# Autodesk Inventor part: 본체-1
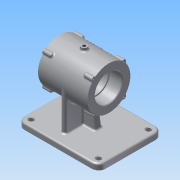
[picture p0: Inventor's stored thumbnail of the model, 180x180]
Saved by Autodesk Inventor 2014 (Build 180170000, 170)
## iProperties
Created: 2016-01
Part Number: 본체-1
Material: 알루미늄 6061
Document SubType Name: Modeling
Designer: Administrator
Density: 2.71 g/cm^3
Appearance: 알루미늄 - 평지
Mass: 1037.38 g
Surface Area: 821.121 cm^2
Volume: 382.798 cm^3
Author: Administrator
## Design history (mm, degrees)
sketch "스케치1"
  geometry: C1 r 37 at (0, 0); 1 further point
  constraints: 1 centre point, 1 coincident
  dimensions: "d0" = 74 diameter of C1
extrude "돌출1" new body sketch "스케치1" stored distance "d1" = 85; taper "d2" = 0 deg
sketch "스케치2"
  geometry: L1 (0, 0)-(26.163, 26.163); L2 (0, 0)-(37, 0); C1 r 3.5 at (26.163, 26.163)
  constraints: 4 end point, 1 centre point, 1 coincident, 1 equal length, 1 horizontal, 2 other
  dimensions: "d3" = 45 deg angle of L2 L1; "d4" = 7 diameter of C1
extrude "돌출2" join sketch "스케치2" distance "d5" = 15; taper "d6" = 0 deg
node "작업 평면1"
sketch "스케치3"
  geometry: L1 (55, 80)-(-55, 80); L2 (-55, 80)-(-55, -60); L3 (-55, -60)-(55, -60); L4 (55, -60)-(55, 80); L5 (23.574, 42.5)-(-23.574, 42.5) reference; 1 further point
  constraints: 8 end point, 2 parallel, 1 horizontal, 1 perpendicular
  dimensions: "d11" = 37.5 distance between parallel lines of L1 L5; "d12" = 140 distance between parallel lines of L3 L1; "d13" = 55 distance from line of point (0, 0) L4; "d14" = 110 distance between parallel lines of L2 L4
extrude "돌출3" join sketch "스케치3" distance "d15" = 10; taper "d16" = 0 deg
sketch "스케치4"
  geometry: L1 (37, 42.5)-(37, -42.5) reference; L2 (37, -42.5)-(-37, -42.5) reference; L3 (-37, -42.5)-(-37, 42.5) reference; L4 (-37, 42.5)-(37, 42.5) reference; L5 (-80, 80)-(-70, 80) reference; L6 (-70, 80)-(-70, -60) reference; L7 (-70, -60)-(-80, -60) reference; L8 (-80, -60)-(-80, 80) reference; L9 (-70, 25)-(-19.194, 16.953); L10 (-70, 0)-(0, 0); L11 (-70, -25)-(-19.194, -16.953); L12 (-19.194, 16.953)-(-19.194, -16.953); L13 (-70, -25)-(-70, 25)
  constraints: 10 end point, 2 perpendicular, 2 point on line, 2 symmetric about line, 1 collinear
  dimensions: "d17" = 25 distance of L9.start L10.start; "d18" = 99 deg angle of L6 L9; "d19" = 56.19381 distance between parallel lines of L1 L12
extrude "돌출4" join sketch "스케치4" stored distance "d20" = 12; taper "d21" = 0 deg
sketch "스케치5"
  geometry: L1 (55, -70)-(55, -80) reference; L2 (55, -80)-(-55, -80) reference; L3 (-55, -80)-(-55, -70) reference; L4 (-55, -70)-(-6, -70) reference; L5 (-6, -70)-(-6, -36.51) reference; L6 (6, -36.51)-(6, -70) reference; L7 (6, -70)-(55, -70) reference; L8 (-37, 0)-(37, 0); L9 (37, 0)-(37, -70); L10 (37, -70)-(-37, -70); L11 (-37, -70)-(-37, 0); A1 r 37 centre (0, 0) between (6, -36.51) and (-6, -36.51) reference; 2 further points
  constraints: 8 end point, 2 parallel, 2 tangent, 1 coincident, 1 horizontal, 1 midpoint, 1 perpendicular, 1 point on line
extrude "돌출5" join sketch "스케치5" stored distance "d22" = 8; taper "d23" = 0 deg
fillet "모깎기1" dims "d24" = 12
sketch "스케치7"
  geometry: C1 r 4 at (-43, 48); C2 r 4 at (43, 48); C3 r 4 at (43, -68); C4 r 4 at (-43, -68); A1 r 12 centre (-43, -68) between (-55, -68) and (-43, -80) reference; A2 r 12 centre (43, -68) between (43, -80) and (55, -68) reference; A3 r 12 centre (43, 48) between (55, 48) and (43, 60) reference; A4 r 12 centre (-43, 48) between (-43, 60) and (-55, 48) reference; 1 further point
  constraints: 4 centre point, 4 coincident
  dimensions: "d25" = 8 diameter of C1; "d26" = 8 diameter of C2; "d27" = 8 diameter of C3; "d28" = 8 diameter of C4
extrude "돌출6" cut sketch "스케치7" distance "d29" = 15; taper "d30" = 0 deg
sketch "스케치8"
  geometry: L1 (55, 68)-(55, -48) reference; L2 (-43, 80)-(43, 80) reference; L3 (55, 68)-(55, -48) reference; L4 (43, -60)-(-43, -60) reference; L5 (-55, -48)-(-55, 68) reference; L6 (23.226, 65)-(-23.226, 65); L7 (-40, 48.226)-(-40, -28.226); L8 (-23.226, -45)-(23.226, -45); L9 (40, -28.226)-(40, 48.226); C1 r 4 at (43, 68) reference; C2 r 4 at (-43, -48) reference; C3 r 4 at (43, -48) reference; C4 r 4 at (-43, 68) reference; A1 r 20 centre (43, 68) between (23.226, 65) and (40, 48.226); A2 r 12 centre (-43, 68) between (-43, 80) and (-55, 68) reference; A3 r 12 centre (43, 68) between (55, 68) and (43, 80) reference; A4 r 12 centre (43, -48) between (43, -60) and (55, -48) reference; A5 r 12 centre (-43, -48) between (-55, -48) and (-43, -60) reference; A6 r 20 centre (-43, -48) between (-23.226, -45) and (-40, -28.226); A7 r 20 centre (-43, 68) between (-40, 48.226) and (-23.226, 65); A8 r 20 centre (43, -48) between (40, -28.226) and (23.226, -45); 1 further point
  constraints: 8 end point, 8 point on circle, 4 centre point, 4 coincident, 2 parallel, 1 horizontal, 1 perpendicular
  dimensions: "d33" = 40 diameter of A1; "d35" = 40 diameter of A6; "d36" = 40 diameter of A7; "d37" = 40 diameter of A8; "d38" = 15 distance between parallel lines of L1 L9; "d39" = 15 distance between parallel lines of L2 L6; "d40" = 15 distance between parallel lines of L5 L7; "d41" = 15 distance between parallel lines of L4 L8
extrude "돌출7" cut sketch "스케치8" distance "d42" = 5; taper "d43" = 0 deg
hole "구멍1" diameter "d46" = 47; stored, may be unused: countersink angle "d50" = 90 deg, drill point angle "d52" = 0 deg; dims "d44" = 10, "d45" = 10, "d47" = 6, "d48" = 4, "d49" = 2, "d51" = 22
hole "구멍2" diameter "d55" = 42; stored, may be unused: countersink angle "d59" = 90 deg, drill point angle "d61" = 0 deg; dims "d53" = 10, "d54" = 10, "d56" = 6, "d57" = 4, "d58" = 2, "d60" = 41
hole "구멍3" diameter "d64" = 47; stored, may be unused: countersink angle "d68" = 90 deg, drill point angle "d70" = 0 deg; dims "d62" = 10, "d63" = 10, "d65" = 6, "d66" = 4, "d67" = 2, "d69" = 22
node "작업 평면2"
sketch "스케치9"
  geometry: C1 r 5 at (0, 0); 1 further point
  constraints: 1 centre point, 1 coincident
  dimensions: "d72" = 10 diameter of C1
extrude "돌출8" join sketch "스케치9" stored distance "d73" = 5; taper "d74" = 0 deg
hole "구멍4" diameter "d77" = 5.188; stored, may be unused: countersink angle "d81" = 90 deg, drill point angle "d83" = 0 deg; dims "d78" = 100, "d79" = 4, "d80" = 2, "d82" = 150, "d84" = 10, "d85" = 10
fillet "모깎기2" dims "d86" = 0.3
fillet "모깎기3" dims "d87" = 3
fillet "모깎기4" dims "d88" = 1
sketch "스케치12"
  geometry: A1 r 3.5 centre (26.163, 26.163) between (28.518, 23.574) and (23.574, 28.518) reference; 1 further point
  constraints: 1 coincident
hole "구멍5" sketch "스케치12" at (26.163, 26.163) diameter "d89" = 3.242; stored, may be unused: countersink angle "d93" = 90 deg, drill point angle "d95" = 118 deg; dims "d90" = 9, "d91" = 4, "d92" = 2, "d94" = 11
chamfer "모따기1" distance "d99" = 1; stored, may be unused: second distance "d100" = 2, angle "d101" = 45 deg
fillet "모깎기5" dims "d102" = 4
fillet "모깎기6" dims "d103" = 3
fillet "모깎기7" dims "d104" = 3
fillet "모깎기8" dims "d105" = 3
fillet "모깎기9" dims "d106" = 3
fillet "모깎기10" dims "d107" = 3
fillet "모깎기11" dims "d108" = 3
fillet "모깎기12" dims "d109" = 3
fillet "모깎기13" dims "d110" = 3
fillet "모깎기14" dims "d111" = 3
fillet "모깎기15" dims "d112" = 3
fillet "모깎기16" dims "d113" = 3
sketch "스케치13"
  geometry: L1 (0, 0)-(41.197, 41.197); L2 (0, 0)-(58.261, 0); C1 r 1.621 at (26.163, 26.163) reference; C2 r 1.621 at (-26.163, 26.163) reference; C3 r 1.621 at (-26.163, -26.163) reference; C4 r 1.621 at (26.163, -26.163) reference; C5 r 24.5 at (0, 0) reference; A1 r 37 centre (0, 0) between (29.78, -21.959) and (29.78, 21.959) reference; A2 r 3 centre (32.194, 23.739) between (29.41, 24.858) and (29.78, 21.959) reference; A3 r 3.5 centre (26.163, 26.163) between (29.41, 24.858) and (24.858, 29.41) reference; A4 r 3 centre (23.739, 32.194) between (21.959, 29.78) and (24.858, 29.41) reference; A5 r 37 centre (0, 0) between (21.959, 29.78) and (-21.959, 29.78) reference; A6 r 3 centre (-23.739, 32.194) between (-24.858, 29.41) and (-21.959, 29.78) reference; A7 r 3.5 centre (-26.163, 26.163) between (-24.858, 29.41) and (-29.41, 24.858) reference; A8 r 3 centre (-32.194, 23.739) between (-29.78, 21.959) and (-29.41, 24.858) reference; A9 r 37 centre (0, 0) between (-29.78, 21.959) and (-29.78, -21.959) reference; A10 r 3 centre (-32.194, -23.739) between (-29.41, -24.858) and (-29.78, -21.959) reference; A11 r 3.5 centre (-26.163, -26.163) between (-29.41, -24.858) and (-24.858, -29.41) reference; A12 r 3 centre (-23.739, -32.194) between (-21.959, -29.78) and (-24.858, -29.41) reference; A13 r 37 centre (0, 0) between (-21.959, -29.78) and (21.959, -29.78) reference; A14 r 3 centre (23.739, -32.194) between (24.858, -29.41) and (21.959, -29.78) reference; A15 r 3.5 centre (26.163, -26.163) between (24.858, -29.41) and (29.41, -24.858) reference; A16 r 3 centre (32.194, -23.739) between (29.78, -21.959) and (29.41, -24.858) reference
  constraints: 4 end point, 1 equal length, 1 horizontal
  dimensions: "d114" = 45 deg angle of L2 L1
node "작업 평면3"
sketch "스케치14"
  geometry: L1 (36.584, 0)-(5.53, 0) reference; 2 further points
  constraints: 1 coincident, 1 other
  dimensions: "d115" = 42.5 distance from line of point (0, -42.5) L1
feature "엠보싱1" sketch "스케치14" dims "d116" = 0.5, "d117" = 0
node "솔리드1"
pattern_circular "원형 패턴1" dims angle "d8" = 360 deg
mirror "대칭1"
pattern_circular "원형 패턴2" dims angle "d97" = 360 deg
mirror "대칭2"
node "절단 모서리 투영1"
node "절단 모서리 투영2"
node "절단 모서리 투영3"
other parameters: "d71" = -122
